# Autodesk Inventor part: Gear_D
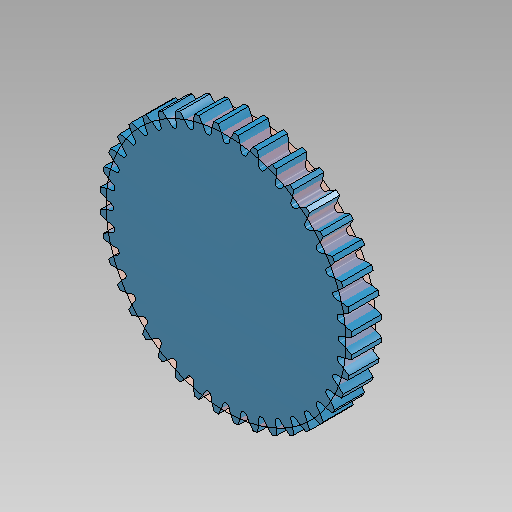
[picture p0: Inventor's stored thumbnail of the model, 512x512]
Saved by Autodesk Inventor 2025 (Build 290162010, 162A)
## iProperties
Created: 2024-10
Part Number: Gear_D
Material: Generic
Document SubType Name: Modeling
Designer: Dennis
Mass: 50.4086 g
Surface Area: 151.33 cm^2
Volume: 50.4086 cm^3
Density: 1 g/cm^3
Appearance: Sky Blue Dark
Author: Dennis
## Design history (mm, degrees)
sketch "Sketch1"
  geometry: C1 r 37.5 at (0, 0) reference; C2 r 37.588 at (0, 0) reference; C3 r 40 at (0, 0) reference; A1 r 42 centre (0, 0) between (-2.536, 41.923) and (2.536, 41.923) reference; 38 further points
  constraints: 4 centre point, 2 point on circle, 83 other
extrude "Extrusion1" join sketch "Sketch1" distance "d0" = 10 (= FaceWidth); taper "d1" = 0 deg
extrude "Extrusion2" cut sketch "Sketch1" extent not by distance; stored distance "d2" = 0; taper "d3" = 0 deg
sketch "Sketch2"
  geometry: L1 (-2.536, -10)-(2.536, -10) reference; L2 (0, -10)-(5, -10); L3 (5, -10)-(5, -15); L4 (5, -15)-(2.5, -15); L5 (2.5, -15)-(2.5, -20); L6 (2.5, -20)-(0, -20); L7 (0, -20)-(0, -10); 1 further point
  constraints: 12 end point, 4 perpendicular, 1 horizontal, 1 midpoint, 1 parallel, 1 vertical
  dimensions: "d7" = 5 diameter of L5 L7; "d8" = 10 diameter of L3 L7; "d9" = 5 distance of L2.end L3.end
revolve "Revolution1" sketch "Sketch2" stored, may be unused: angle "d10" = 90 deg
sketch "Sketch3"
  geometry: C1 r 40 at (0, 0); 1 further point
  constraints: 1 centre point, 1 coincident
  dimensions: "d11" = 80 diameter of C1
extrude_surface "ExtrusionSrf1" sketch "Sketch3" dims "d12" = 10, "d13" = 0
body "Solid1"
pattern_circular "Circular Pattern1" dims angle "d5" = 360 deg
body "Srf1"
other parameters: "Module" = 2 [user parameter], "PressureAngle" = 20 deg [user parameter], "UnitProfileClearance" = 2.5 [user parameter], "UnitRoundRadius" = 3.5 [user parameter], "HeadDiameter" = 84 [user parameter], "RootDiameter" = 75 [user parameter], "BaseDiameter" = 75.17541 [user parameter], "FaceWidth" = 10 [user parameter; used in 1 equation term], "HelixAngle" = 0 [user parameter], "UnitCorrection" = 0 [user parameter], "UnitAddendumModification" = 0 [user parameter], "CircularPitch" = 36 deg [user parameter], "UnitBacklashShift" = 0 [user parameter], "TotalToolShift" = 0 [user parameter], "IsInternal" = 0 [user parameter]
